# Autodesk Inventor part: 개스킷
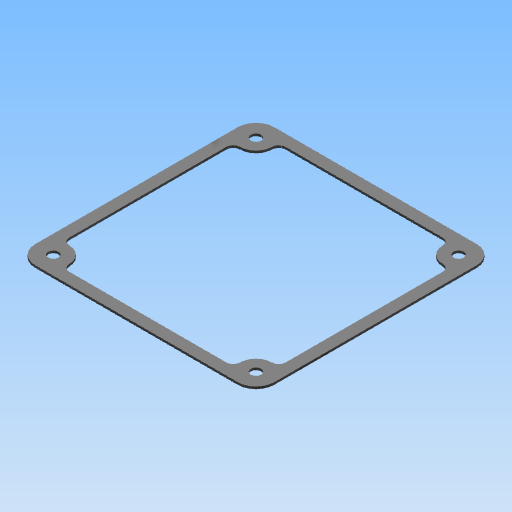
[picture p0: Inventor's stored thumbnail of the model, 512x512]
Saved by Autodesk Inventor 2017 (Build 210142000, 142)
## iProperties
Created: 2019-04
Part Number: 개스킷
Material: 고무
Document SubType Name: Modeling
Designer: mduedu
Density: 0.93 g/cm^3
Mass: 2.09699 g
Surface Area: 53.3016 cm^2
Volume: 2.25483 cm^3
Appearance: 고무 - 검은색 - 버전 1.1
Author: mduedu
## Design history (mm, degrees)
sketch "스케치1"
  geometry: L1 (52.5, 52.5)-(-52.5, 52.5); L2 (-52.5, 52.5)-(-52.5, -52.5); L3 (-52.5, -52.5)-(52.5, -52.5); L4 (52.5, -52.5)-(52.5, 52.5); L5 (52.5, 52.5)-(-52.5, -52.5); L6 (-52.5, 52.5)-(52.5, -52.5); 1 further point
  constraints: 12 end point, 2 midpoint, 2 parallel, 1 horizontal, 1 perpendicular
  dimensions: "d0" = 105 distance of L3.end L2.end; "d1" = 105 distance of L2.end L1.end
extrude "돌출1" new body sketch "스케치1" distance "d2" = 1; taper "d3" = 0 deg
sketch "스케치2"
  geometry: L1 (-52.5, -52.5)-(52.5, -52.5) reference; L2 (52.5, -52.5)-(52.5, 52.5) reference; L3 (52.5, 52.5)-(-52.5, 52.5) reference; L4 (-52.5, 52.5)-(-52.5, -52.5) reference; L5 (-47.5, 47.5)-(47.5, 47.5); L6 (47.5, 47.5)-(47.5, -47.5); L7 (47.5, -47.5)-(-47.5, -47.5); L8 (-47.5, -47.5)-(-47.5, 47.5); 1 further point
  constraints: 8 end point, 3 other
  dimensions: "d4" = 5 distance between parallel lines of L5 L3
extrude "돌출2" cut sketch "스케치2" stored distance "d5" = 1; taper "d6" = 0 deg
fillet "모깎기1" dims "d7" = 8
sketch "스케치3"
  geometry: C1 r 7 at (-44.5, 44.5); C2 r 7 at (-44.5, -44.5); C3 r 7 at (44.5, -44.5); C4 r 7 at (44.5, 44.5); A1 r 8 centre (-44.5, 44.5) between (-44.5, 52.5) and (-52.5, 44.5) reference; A2 r 8 centre (-44.5, -44.5) between (-52.5, -44.5) and (-44.5, -52.5) reference; A3 r 8 centre (44.5, -44.5) between (44.5, -52.5) and (52.5, -44.5) reference; A4 r 8 centre (44.5, 44.5) between (52.5, 44.5) and (44.5, 52.5) reference; 1 further point
  constraints: 4 centre point, 4 coincident, 3 equal radius
  dimensions: "d18" = 14 diameter of C1
extrude "돌출3" join sketch "스케치3" stored distance "d8" = 1; taper "d9" = 0 deg
fillet "모깎기2" dims "d10" = 3
sketch "스케치4"
  geometry: A1 r 8 centre (-44.5, 44.5) between (-44.5, 52.5) and (-52.5, 44.5) reference; A2 r 8 centre (44.5, 44.5) between (52.5, 44.5) and (44.5, 52.5) reference; A3 r 8 centre (44.5, -44.5) between (44.5, -52.5) and (52.5, -44.5) reference; A4 r 8 centre (-44.5, -44.5) between (-52.5, -44.5) and (-44.5, -52.5) reference; 5 further points
  constraints: 4 coincident
hole "구멍1" sketch "스케치4" at (-44.5, 44.5), (44.5, 44.5), (44.5, -44.5), (-44.5, -44.5) diameter "d11" = 4.5; stored, may be unused: countersink angle "d15" = 90 deg, drill point angle "d17" = 118 deg; dims "d12" = 6, "d13" = 4, "d14" = 2, "d16" = 8
node "솔리드1"
node "투영된 루프1"
